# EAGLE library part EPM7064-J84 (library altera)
EPM7064 MAX 7000 family
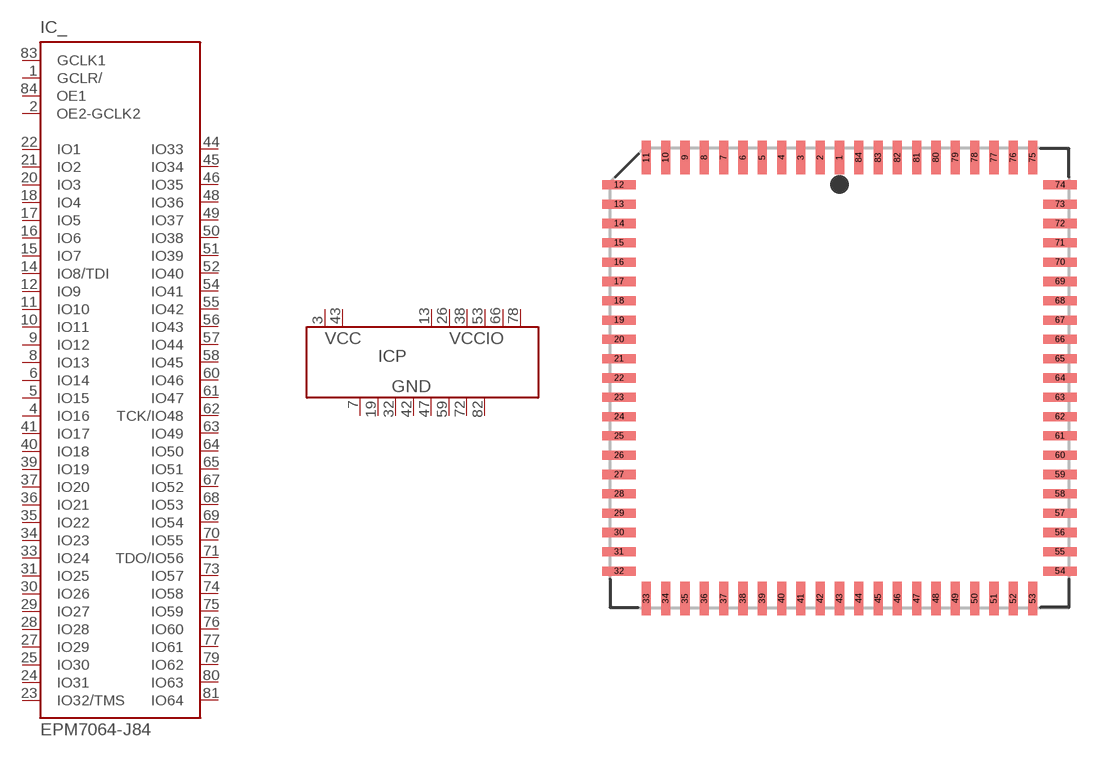
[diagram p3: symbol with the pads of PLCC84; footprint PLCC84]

Designator prefix IC; gates _=EPM7064S P=PWR8-2-6

## EPM7064-J84 (MPN: EPM7064SLC84-10N; OC_FARNELL: 1549457; OC_NEWARK: 51R9623)  [PLCC84]
1  _:GCLR/  in
2  _:OE2-GCLK2  in
3  P:VCC  pwr
4  _:IO16
5  _:IO15
6  _:IO14
7  P:GND  pwr
8  _:IO13
9  _:IO12
10  _:IO11
11  _:IO10
12  _:IO9
13  P:VCCIO  pwr
14  _:IO8/TDI
15  _:IO7
16  _:IO6
17  _:IO5
18  _:IO4
19  P:GND  pwr
20  _:IO3
21  _:IO2
22  _:IO1
23  _:IO32/TMS
24  _:IO31
25  _:IO30
26  P:VCCIO  pwr
27  _:IO29
28  _:IO28
29  _:IO27
30  _:IO26
31  _:IO25
32  P:GND  pwr
33  _:IO24
34  _:IO23
35  _:IO22
36  _:IO21
37  _:IO20
38  P:VCCIO  pwr
39  _:IO19
40  _:IO18
41  _:IO17
42  P:GND  pwr
43  P:VCC  pwr
44  _:IO33
45  _:IO34
46  _:IO35
47  P:GND  pwr
48  _:IO36
49  _:IO37
50  _:IO38
51  _:IO39
52  _:IO40
53  P:VCCIO  pwr
54  _:IO41
55  _:IO42
56  _:IO43
57  _:IO44
58  _:IO45
59  P:GND  pwr
60  _:IO46
61  _:IO47
62  _:TCK/IO48
63  _:IO49
64  _:IO50
65  _:IO51
66  P:VCCIO  pwr
67  _:IO52
68  _:IO53
69  _:IO54
70  _:IO55
71  _:TDO/IO56
72  P:GND  pwr
73  _:IO57
74  _:IO58
75  _:IO59
76  _:IO60
77  _:IO61
78  P:VCCIO  pwr
79  _:IO62
80  _:IO63
81  _:IO64
82  P:GND  pwr
83  _:GCLK1  in
84  _:OE1  in

## Footprint PLCC84 (pad centres in mm)
Plastic J-Lead Chip Carrier
smd 0.6 x 2.2: 1 0,14.5; 2 -1.27,14.5; 3 -2.54,14.5; 4 -3.81,14.5; 5 -5.08,14.5; 6 -6.35,14.5; 7 -7.62,14.5; 8 -8.89,14.5; 9 -10.16,14.5; 10 -11.43,14.5; 11 -12.7,14.5; 33 -12.7,-14.5; 34 -11.43,-14.5; 35 -10.16,-14.5; 36 -8.89,-14.5; 37 -7.62,-14.5; 38 -6.35,-14.5; 39 -5.08,-14.5; 40 -3.81,-14.5; 41 -2.54,-14.5; 42 -1.27,-14.5; 43 0,-14.5; 44 1.27,-14.5; 45 2.54,-14.5; 46 3.81,-14.5; 47 5.08,-14.5; 48 6.35,-14.5; 49 7.62,-14.5; 50 8.89,-14.5; 51 10.16,-14.5; 52 11.43,-14.5; 53 12.7,-14.5; 75 12.7,14.5; 76 11.43,14.5; 77 10.16,14.5; 78 8.89,14.5; 79 7.62,14.5; 80 6.35,14.5; 81 5.08,14.5; 82 3.81,14.5; 83 2.54,14.5; 84 1.27,14.5
smd 2.2 x 0.6: 12 -14.5,12.7; 13 -14.5,11.43; 14 -14.5,10.16; 15 -14.5,8.89; 16 -14.5,7.62; 17 -14.5,6.35; 18 -14.5,5.08; 19 -14.5,3.81; 20 -14.5,2.54; 21 -14.5,1.27; 22 -14.5,0; 23 -14.5,-1.27; 24 -14.5,-2.54; 25 -14.5,-3.81; 26 -14.5,-5.08; 27 -14.5,-6.35; 28 -14.5,-7.62; 29 -14.5,-8.89; 30 -14.5,-10.16; 31 -14.5,-11.43; 32 -14.5,-12.7; 54 14.5,-12.7; 55 14.5,-11.43; 56 14.5,-10.16; 57 14.5,-8.89; 58 14.5,-7.62; 59 14.5,-6.35; 60 14.5,-5.08; 61 14.5,-3.81; 62 14.5,-2.54; 63 14.5,-1.27; 64 14.5,0; 65 14.5,1.27; 66 14.5,2.54; 67 14.5,3.81; 68 14.5,5.08; 69 14.5,6.35; 70 14.5,7.62; 71 14.5,8.89; 72 14.5,10.16; 73 14.5,11.43; 74 14.5,12.7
